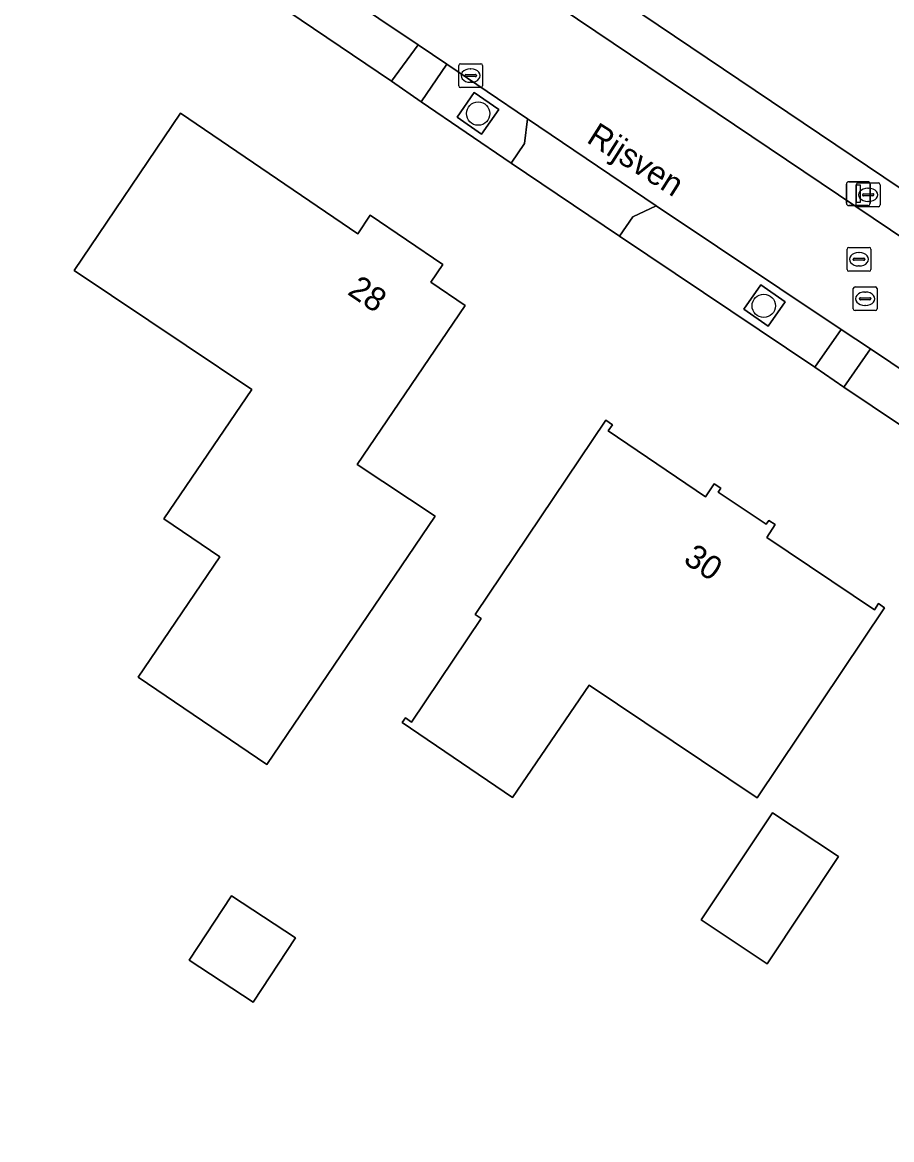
# Model space of a CAD drawing. Extents: x 163266 to 164362, y 381528 to 382286.
# Drawn here: x 164023.78 to 164060.23, y 381668.37 to 381715.24 of the extents above; entities that cross this region are included whole.
import ezdxf

# ---------------------------------------------------------------- set-up
doc = ezdxf.new("R2010")
doc.units = 0
for name, color, linetype in [('IMGEO_Boom', 7, 'Continuous'), ('IMGEO_Brandkraan', 7, 'Continuous'), ('IMGEO_Erf', 7, 'Continuous'), ('IMGEO_Groenvoorziening', 7, 'Continuous'), ('IMGEO_Haag', 7, 'Continuous'), ('IMGEO_Kolk', 7, 'Continuous'), ('IMGEO_Lichtmast', 7, 'Continuous'), ('IMGEO_Openbare_ruimte_label', 7, 'Continuous'), ('IMGEO_Pand', 7, 'Continuous'), ('IMGEO_Pand_nummerreeks', 7, 'Continuous'), ('IMGEO_Rijbaan_lokaal_open', 7, 'Continuous'), ('IMGEO_Rioolput', 7, 'Continuous'), ('IMGEO_Voetpad_halfverhard', 7, 'Continuous'), ('IMGEO_Voetpad_open', 7, 'Continuous')]:
    doc.layers.add(name, color=color, linetype=linetype)

msp = doc.modelspace()

# ---------------------------------------------------------------- linework, layer by layer
at = {"layer": 'IMGEO_Boom'}
for centre in [(164042.889, 381711.409), (164054.865, 381703.346)]:
    msp.add_circle(centre, 0.489, dxfattribs=at)
at = {"layer": 'IMGEO_Brandkraan'}
for p, q in [((164058.82, 381708.502), (164059.672, 381708.502)), ((164058.745, 381707.576), (164058.745, 381708.428)), ((164059.004, 381707.996), (164059.004, 381708.008)), ((164059.047, 381708.045), (164059.445, 381708.045)), ((164059.233, 381708.282), (164059.258, 381708.282)), ((164059.488, 381708.008), (164059.488, 381707.996)), ((164059.746, 381708.428), (164059.746, 381707.576)), ((164059.672, 381707.502), (164058.82, 381707.502)), ((164059.442, 381707.959), (164059.044, 381707.959)), ((164059.256, 381707.722), (164059.231, 381707.722))]:
    msp.add_line(p, q, dxfattribs=at)
for points in [[(164058.82, 381708.502), (164059.672, 381708.502)], [(164058.745, 381707.576), (164058.745, 381708.428)], [(164059.746, 381708.428), (164059.746, 381707.576)], [(164059.672, 381707.502), (164058.82, 381707.502)]]:
    msp.add_lwpolyline(points, dxfattribs=at)
for centre, radius, start, end in [((164058.822, 381708.426), 0.0765, 91.552, 178.448), ((164058.822, 381708.426), 0.0765, 91.552, 178.448), ((164059.67, 381708.426), 0.0765, 1.552, 88.448), ((164059.67, 381708.426), 0.0765, 1.552, 88.448), ((164059.044, 381708.005), 0.0403, 85.8775, 175.7526), ((164059.041, 381707.995), 0.0366, 178.938, 274.7102), ((164059.445, 381708.002), 0.043, 264.8664, 352.4533), ((164059.449, 381708.007), 0.0386, 1.7309, 96.639), ((164058.822, 381707.578), 0.0765, 181.552, 268.448), ((164058.822, 381707.578), 0.0765, 181.552, 268.448), ((164059.67, 381707.578), 0.0765, 271.552, 358.448), ((164059.67, 381707.578), 0.0765, 271.552, 358.448)]:
    msp.add_arc(centre, radius, start, end, dxfattribs=at)
for centre, major_axis, ratio, start_param, end_param in [((164059.232, 381708.002), (-0.387, 0.002), 0.722429, 4.712389, 7.853982), ((164059.257, 381708.002), (-0.39, 0.002), 0.717154, 1.570796, 4.712389)]:
    msp.add_ellipse(centre, major_axis=major_axis, ratio=ratio, start_param=start_param, end_param=end_param, dxfattribs=at)
at = {"layer": 'IMGEO_Erf'}
for points in [[(164078.899, 381686.041), (164073.867, 381689.437), (164069.267, 381692.537), (164067.04, 381694.07), (164062.928, 381696.773), (164058.221, 381699.932), (164057.006, 381700.767), (164048.821, 381706.271), (164044.279, 381709.335), (164040.497, 381711.904), (164039.261, 381712.764), (164030.048, 381719.001), (164027.004, 381721.09), (164026.19, 381719.875), (164024.486, 381721.003), (164007.31, 381732.546)], [(164031.559, 381727.86), (164063.287, 381706.457), (164064.424, 381705.642), (164066.43, 381704.274), (164071.069, 381701.241), (164082.518, 381693.469), (164087.121, 381690.39), (164089.32, 381688.957), (164093.825, 381685.899), (164104.06, 381678.938), (164146.786, 381709.887), (164146.237, 381710.272), (164149.576, 381715.022), (164151.746, 381713.502), (164150.775, 381712.777), (164154.802, 381715.694), (164148.759, 381719.82), (164152.254, 381724.987)]]:
    msp.add_lwpolyline(points, dxfattribs=at)
for points in [[(164032.057, 381692.817), (164029.715, 381694.406), (164033.399, 381699.834), (164030.644, 381701.682), (164025.947, 381704.831), (164030.414, 381711.426), (164037.85, 381706.364), (164038.367, 381707.142), (164041.406, 381705.079), (164040.901, 381704.335), (164042.34, 381703.354), (164037.818, 381696.691), (164041.088, 381694.53), (164034.026, 381684.108), (164028.631, 381687.769)], [(164048.244, 381698.549), (164048.519, 381698.358), (164048.34, 381698.1), (164052.42, 381695.336), (164052.789, 381695.886), (164053.065, 381695.701), (164052.953, 381695.535), (164054.961, 381694.186), (164055.074, 381694.347), (164055.344, 381694.17), (164054.988, 381693.627), (164059.504, 381690.594), (164059.681, 381690.855), (164059.934, 381690.681), (164054.595, 381682.706), (164047.542, 381687.431), (164044.336, 381682.718), (164039.706, 381685.868), (164039.846, 381686.066), (164040.094, 381685.887), (164043.017, 381690.236), (164042.758, 381690.407)], [(164055.228, 381682.088), (164057.998, 381680.25), (164055.013, 381675.75), (164052.237, 381677.592)], [(164032.547, 381678.606), (164035.23, 381676.843), (164033.45, 381674.135), (164030.767, 381675.898)]]:
    msp.add_lwpolyline(points, close=True, dxfattribs=at)
at = {"layer": 'IMGEO_Groenvoorziening'}
for points in [[(164043.75, 381711.577), (164042.724, 381712.291), (164042.009, 381711.266), (164043.035, 381710.551)], [(164055.766, 381703.517), (164054.74, 381704.232), (164054.026, 381703.206), (164055.051, 381702.491)]]:
    msp.add_lwpolyline(points, close=True, dxfattribs=at)
at = {"layer": 'IMGEO_Haag'}
for points in [[(164043.75, 381711.577), (164042.724, 381712.291), (164042.009, 381711.266), (164043.035, 381710.551)], [(164055.766, 381703.517), (164054.74, 381704.232), (164054.026, 381703.206), (164055.051, 381702.491)]]:
    msp.add_lwpolyline(points, close=True, dxfattribs=at)
at = {"layer": 'IMGEO_Kolk'}
for p, q in [((164042.072, 381712.576), (164042.072, 381713.428)), ((164042.147, 381713.502), (164042.999, 381713.502)), ((164042.56, 381713.282), (164042.585, 381713.282)), ((164043.073, 381713.428), (164043.073, 381712.576)), ((164042.331, 381712.996), (164042.331, 381713.008)), ((164042.769, 381712.959), (164042.371, 381712.959)), ((164042.374, 381713.045), (164042.772, 381713.045)), ((164042.583, 381712.722), (164042.558, 381712.722)), ((164042.815, 381713.008), (164042.815, 381712.996)), ((164042.999, 381712.502), (164042.147, 381712.502))]:
    msp.add_line(p, q, dxfattribs=at)
for points in [[(164042.072, 381712.576), (164042.072, 381713.428)], [(164042.147, 381713.502), (164042.999, 381713.502)], [(164043.073, 381713.428), (164043.073, 381712.576)], [(164042.999, 381712.502), (164042.147, 381712.502)]]:
    msp.add_lwpolyline(points, dxfattribs=at)
for centre, radius, start, end in [((164042.149, 381713.426), 0.0765, 91.552, 178.448), ((164042.149, 381713.426), 0.0765, 91.552, 178.448), ((164042.997, 381713.426), 0.0765, 1.552, 88.448), ((164042.997, 381713.426), 0.0765, 1.552, 88.448), ((164042.371, 381713.005), 0.0403, 85.8775, 175.7526), ((164042.368, 381712.995), 0.0366, 178.938, 274.7102), ((164042.772, 381713.002), 0.043, 264.8664, 352.4533), ((164042.776, 381713.007), 0.0386, 1.7309, 96.639), ((164042.149, 381712.578), 0.0765, 181.552, 268.448), ((164042.149, 381712.578), 0.0765, 181.552, 268.448), ((164042.997, 381712.578), 0.0765, 271.552, 358.448), ((164042.997, 381712.578), 0.0765, 271.552, 358.448)]:
    msp.add_arc(centre, radius, start, end, dxfattribs=at)
for centre, major_axis, ratio, start_param, end_param in [((164042.559, 381713.002), (-0.387, 0.002), 0.722429, 4.712389, 7.853982), ((164042.584, 381713.002), (-0.39, 0.002), 0.717154, 1.570796, 4.712389)]:
    msp.add_ellipse(centre, major_axis=major_axis, ratio=ratio, start_param=start_param, end_param=end_param, dxfattribs=at)
at = {"layer": 'IMGEO_Lichtmast'}
for p, q in [((164058.334, 381707.649), (164058.334, 381708.449)), ((164058.334, 381708.449), (164058.334, 381707.649)), ((164058.434, 381708.549), (164059.224, 381708.549)), ((164059.224, 381708.549), (164058.434, 381708.549)), ((164059.324, 381708.449), (164059.324, 381707.649)), ((164059.324, 381707.649), (164059.324, 381708.449)), ((164059.224, 381707.549), (164058.434, 381707.549)), ((164058.434, 381707.549), (164059.224, 381707.549))]:
    msp.add_line(p, q, dxfattribs=at)
msp.add_lwpolyline([(164058.754, 381708.424), (164058.904, 381708.424), (164058.904, 381707.674), (164058.754, 381707.674), (164058.754, 381708.424)], dxfattribs=at)
for centre, start, end in [((164058.434, 381708.449), 90, 180), ((164058.434, 381708.449), 90, 180), ((164059.224, 381708.449), 0, 90), ((164059.224, 381708.449), 360, 90), ((164058.434, 381707.649), 180, 270), ((164058.434, 381707.649), 180, 270), ((164059.224, 381707.649), 270, 0), ((164059.224, 381707.649), 270, 0)]:
    msp.add_arc(centre, 0.1, start, end, dxfattribs=at)
at = {"layer": 'IMGEO_Pand'}
for points in [[(164029.715, 381694.406), (164032.057, 381692.817), (164028.631, 381687.769), (164034.026, 381684.108), (164041.088, 381694.53), (164037.818, 381696.691), (164042.34, 381703.354), (164040.901, 381704.335), (164041.406, 381705.079), (164038.367, 381707.142), (164037.85, 381706.364), (164030.414, 381711.426), (164025.947, 381704.831), (164030.644, 381701.682), (164033.399, 381699.834)], [(164054.595, 381682.706), (164059.934, 381690.681), (164059.681, 381690.855), (164059.504, 381690.594), (164054.988, 381693.627), (164055.344, 381694.17), (164055.074, 381694.347), (164054.961, 381694.186), (164052.953, 381695.535), (164053.065, 381695.701), (164052.789, 381695.886), (164052.42, 381695.336), (164048.34, 381698.1), (164048.519, 381698.358), (164048.244, 381698.549), (164042.758, 381690.407), (164043.017, 381690.236), (164040.094, 381685.887), (164039.846, 381686.066), (164039.706, 381685.868), (164044.336, 381682.718), (164047.542, 381687.431)], [(164055.013, 381675.75), (164057.998, 381680.25), (164055.228, 381682.088), (164052.237, 381677.592)], [(164030.767, 381675.898), (164033.45, 381674.135), (164035.23, 381676.843), (164032.547, 381678.606)]]:
    msp.add_lwpolyline(points, close=True, dxfattribs=at)
at = {"layer": 'IMGEO_Rijbaan_lokaal_open'}
for points in [[(163999.252, 381744.71), (164008.883, 381735.535), (164016.853, 381730.156), (164018.052, 381729.344), (164026.521, 381723.615), (164031.695, 381720.116), (164032.207, 381719.769), (164040.374, 381714.295), (164041.569, 381713.485), (164044.956, 381711.196), (164050.355, 381707.539), (164058.116, 381702.356), (164059.338, 381701.54), (164063.682, 381698.622), (164068.515, 381695.376), (164069.911, 381694.44), (164075.422, 381690.725), (164080.018, 381687.656), (164081.239, 381686.855), (164087.153, 381682.87)], [(164087.762, 381678.694), (164083.437, 381672.269), (164089.398, 381668.374), (164102.719, 381677.999), (164093.356, 381684.193), (164087.931, 381687.844), (164086.628, 381688.69), (164081.066, 381692.453), (164070.501, 381699.546), (164065.165, 381703.163), (164063.552, 381704.231), (164062.367, 381705.06), (164032.514, 381725.171), (164030.603, 381726.452), (164030.282, 381726.667)]]:
    msp.add_lwpolyline(points, dxfattribs=at)
at = {"layer": 'IMGEO_Rioolput'}
for p, q in [((164058.358, 381704.873), (164058.358, 381705.725)), ((164058.433, 381705.799), (164059.285, 381705.799)), ((164059.359, 381705.725), (164059.359, 381704.873)), ((164058.617, 381705.293), (164058.617, 381705.305)), ((164059.055, 381705.256), (164058.657, 381705.256)), ((164058.66, 381705.342), (164059.058, 381705.342)), ((164058.846, 381705.579), (164058.871, 381705.579)), ((164059.101, 381705.305), (164059.101, 381705.293)), ((164059.285, 381704.799), (164058.433, 381704.799)), ((164058.869, 381705.019), (164058.844, 381705.019)), ((164058.619, 381703.218), (164058.619, 381704.07)), ((164058.694, 381704.144), (164059.546, 381704.144)), ((164059.107, 381703.924), (164059.132, 381703.924)), ((164059.62, 381704.07), (164059.62, 381703.218)), ((164058.878, 381703.638), (164058.878, 381703.65)), ((164059.316, 381703.601), (164058.918, 381703.601)), ((164058.921, 381703.687), (164059.319, 381703.687)), ((164059.13, 381703.364), (164059.105, 381703.364)), ((164059.362, 381703.65), (164059.362, 381703.638)), ((164059.546, 381703.144), (164058.694, 381703.144))]:
    msp.add_line(p, q, dxfattribs=at)
for points in [[(164058.358, 381704.873), (164058.358, 381705.725)], [(164058.433, 381705.799), (164059.285, 381705.799)], [(164059.359, 381705.725), (164059.359, 381704.873)], [(164059.285, 381704.799), (164058.433, 381704.799)], [(164058.619, 381703.218), (164058.619, 381704.07)], [(164058.694, 381704.144), (164059.546, 381704.144)], [(164059.62, 381704.07), (164059.62, 381703.218)], [(164059.546, 381703.144), (164058.694, 381703.144)]]:
    msp.add_lwpolyline(points, dxfattribs=at)
for centre, radius, start, end in [((164058.435, 381705.723), 0.0765, 91.552, 178.448), ((164058.435, 381705.723), 0.0765, 91.552, 178.448), ((164059.283, 381705.723), 0.0765, 1.552, 88.448), ((164059.283, 381705.723), 0.0765, 1.552, 88.448), ((164058.657, 381705.302), 0.0403, 85.8775, 175.7526), ((164058.654, 381705.292), 0.0366, 178.938, 274.7102), ((164059.058, 381705.299), 0.043, 264.8664, 352.4533), ((164059.062, 381705.304), 0.0386, 1.7309, 96.639), ((164058.435, 381704.875), 0.0765, 181.552, 268.448), ((164058.435, 381704.875), 0.0765, 181.552, 268.448), ((164059.283, 381704.875), 0.0765, 271.552, 358.448), ((164059.283, 381704.875), 0.0765, 271.552, 358.448), ((164058.696, 381704.068), 0.0765, 91.552, 178.448), ((164058.696, 381704.068), 0.0765, 91.552, 178.448), ((164059.544, 381704.068), 0.0765, 1.552, 88.448), ((164059.544, 381704.068), 0.0765, 1.552, 88.448), ((164058.918, 381703.647), 0.0403, 85.8775, 175.7526), ((164058.915, 381703.637), 0.0366, 178.938, 274.7102), ((164059.319, 381703.644), 0.043, 264.8664, 352.4533), ((164059.323, 381703.649), 0.0386, 1.7309, 96.639), ((164058.696, 381703.22), 0.0765, 181.552, 268.448), ((164058.696, 381703.22), 0.0765, 181.552, 268.448), ((164059.544, 381703.22), 0.0765, 271.552, 358.448), ((164059.544, 381703.22), 0.0765, 271.552, 358.448)]:
    msp.add_arc(centre, radius, start, end, dxfattribs=at)
for centre, major_axis, ratio, start_param, end_param in [((164058.845, 381705.299), (-0.387, 0.002), 0.722429, 4.712389, 7.853982), ((164058.87, 381705.299), (-0.39, 0.002), 0.717154, 1.570796, 4.712389), ((164059.106, 381703.644), (-0.387, 0.002), 0.722429, 4.712389, 7.853982), ((164059.131, 381703.644), (-0.39, 0.002), 0.717154, 1.570796, 4.712389)]:
    msp.add_ellipse(centre, major_axis=major_axis, ratio=ratio, start_param=start_param, end_param=end_param, dxfattribs=at)
at = {"layer": 'IMGEO_Voetpad_halfverhard'}
for points in [[(164032.514, 381725.171), (164062.367, 381705.06), (164063.287, 381706.457), (164031.559, 381727.86), (164030.603, 381726.452)], [(164030.048, 381719.001), (164039.261, 381712.764), (164040.374, 381714.295), (164032.207, 381719.769), (164031.695, 381720.116), (164030.601, 381719.82)], [(164041.569, 381713.485), (164040.497, 381711.904), (164044.279, 381709.335), (164044.827, 381710.156), (164044.956, 381711.196)], [(164043.035, 381710.551), (164042.009, 381711.266), (164042.724, 381712.291), (164043.75, 381711.577)], [(164048.821, 381706.271), (164057.006, 381700.767), (164058.116, 381702.356), (164050.355, 381707.539), (164049.382, 381707.08)], [(164055.051, 381702.491), (164054.026, 381703.206), (164054.74, 381704.232), (164055.766, 381703.517)], [(164063.682, 381698.622), (164059.338, 381701.54), (164058.221, 381699.932), (164062.928, 381696.773), (164063.47, 381697.624)]]:
    msp.add_lwpolyline(points, close=True, dxfattribs=at)
at = {"layer": 'IMGEO_Voetpad_open'}
for points in [[(164040.374, 381714.295), (164039.261, 381712.764), (164040.497, 381711.904), (164041.569, 381713.485)], [(164044.956, 381711.196), (164044.827, 381710.156), (164044.279, 381709.335), (164048.821, 381706.271), (164049.382, 381707.08), (164050.355, 381707.539)], [(164058.221, 381699.932), (164059.338, 381701.54), (164058.116, 381702.356), (164057.006, 381700.767)]]:
    msp.add_lwpolyline(points, close=True, dxfattribs=at)

# ---------------------------------------------------------------- texts
at = {"layer": 'IMGEO_Openbare_ruimte_label'}
msp.add_text('Rijsven', height=1, rotation=327.6606, dxfattribs=at).set_placement((164047.388, 381710.234))
at = {"layer": 'IMGEO_Pand_nummerreeks'}
for s, rotation, p in [('28', 325.8391, (164037.366, 381703.857)), ('30', 326.0989, (164051.447, 381692.595))]:
    msp.add_text(s, height=1, rotation=rotation, dxfattribs=at).set_placement(p)

doc.saveas('drawing.dxf')
